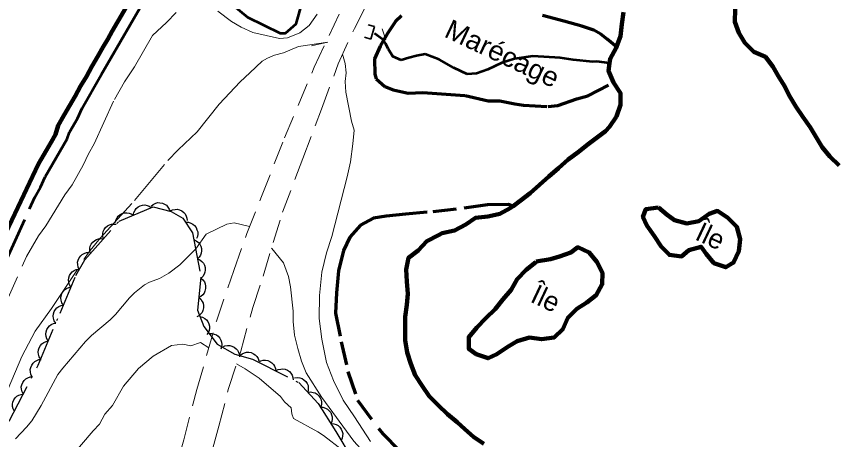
# Model space of a CAD drawing. Extents: x 355726 to 357533, y 5103782 to 5105258.
# Drawn here: x 355974.4 to 356037.4, y 5104645.3 to 5104677.9 of the extents above; entities that cross this region are included whole.
import ezdxf

# ---------------------------------------------------------------- set-up
doc = ezdxf.new("R2010")
doc.units = 0
doc.header["$LTSCALE"] = 0.6
for name, pattern in [('DASH_DOUBLE_DOT', [9.2, 5, -1.2, 0.3, -1.2, 0.3, -1.2]), ('DOT_DASHED', [7.7, 5, -1.2, 0.3, -1.2]), ('LONG_DASHED', [7.5, 6, -1.5]), ('MEDIUM_DASHED', [4.5, 3, -1.5])]:
    doc.linetypes.add(name, pattern=pattern)
for name, color, linetype, lineweight in [('1', 7, 'LONG_DASHED', 53), ('19', 7, 'Continuous', 13), ('2', 7, 'LONG_DASHED', 13), ('26', 7, 'Continuous', 35), ('4', 7, 'DASH_DOUBLE_DOT', 53), ('44', 7, 'Continuous', 25), ('7', 7, 'MEDIUM_DASHED', 70)]:
    doc.layers.add(name, color=color, linetype=linetype, lineweight=lineweight)
doc.layers.add('8', color=7, linetype='Continuous')

msp = doc.modelspace()

# ---------------------------------------------------------------- linework, layer by layer
at = {"layer": '1', "linetype": 'Continuous'}
for points in [[(355990.95, 5104678.76), (355992.11, 5104677.81), (355994.63, 5104676.58), (355995.02, 5104676.56), (355995.85, 5104677.29), (355996.33, 5104679.01)], [(355980.9, 5104673.37), (355983.85, 5104678.49)]]:
    msp.add_lwpolyline(points, dxfattribs=at)
at = {"layer": '1'}
msp.add_lwpolyline([(355973.54, 5104658.98), (355975.81, 5104663.98), (355976.24, 5104664.73), (355976.6, 5104665.53), (355978.29, 5104668.46), (355978.47, 5104668.96), (355979.08, 5104670.01), (355979.43, 5104670.81), (355980.9, 5104673.37)], dxfattribs=at)
at = {"layer": '19', "linetype": 'MEDIUM_DASHED'}
for points in [[(355997.8, 5104670.73), (355999.08, 5104674.22), (356000.32, 5104676.94), (356001.43, 5104679.09), (356002.21, 5104680.3), (356006.1, 5104687.7), (356008.11, 5104691.5), (356009.62, 5104696.76), (356011.14, 5104701.84), (356012.62, 5104707.21), (356014.22, 5104712.09), (356015.74, 5104717.23), (356017.57, 5104723.26), (356018.4, 5104728.58), (356020.43, 5104734.04), (356022.51, 5104739.47), (356025.19, 5104744.96), (356027.66, 5104749.58), (356030.65, 5104755.01), (356033.08, 5104758.13), (356035.37, 5104761.13), (356036.71, 5104764.38), (356036.94, 5104767.51)], [(355973.33, 5104607.29), (355976.87, 5104615.17), (355979.51, 5104621.42), (355981.38, 5104626.83), (355982.76, 5104630.14), (355983.73, 5104632.9), (355985.72, 5104639.37), (355987.22, 5104645.34), (355988.24, 5104649.21), (355989.73, 5104654.44), (355991.06, 5104658.34), (355992.07, 5104661.18), (355993.19, 5104664.01), (355994.95, 5104668.52), (355997.24, 5104673.96), (355999.22, 5104678.15)], [(355973.64, 5104601.69), (355975.44, 5104605.41), (355977.53, 5104610.55), (355979.26, 5104614.32), (355981.26, 5104619.25), (355981.79, 5104620.73), (355982.61, 5104622.54), (355982.76, 5104622.85), (355983.09, 5104623.55), (355984.31, 5104626.76), (355985.46, 5104630.01), (355986.84, 5104635.04), (355987.76, 5104638.42), (355988.77, 5104642.09), (355989.92, 5104646.38), (355990.66, 5104649.27), (355991.6, 5104652.15), (355992.52, 5104655.49), (355993.31, 5104657.91), (355994.8, 5104662.81), (355996.35, 5104666.94), (355997.8, 5104670.73)]]:
    msp.add_lwpolyline(points, dxfattribs=at)
at = {"layer": '2', "linetype": 'Continuous'}
for p, q in [((356002.46, 5104676.91), (356002.74, 5104676.05)), ((355988.51, 5104652.82), (355989.15, 5104652.4))]:
    msp.add_line(p, q, dxfattribs=at)
for points in [[(355982.68, 5104672.82), (355983.45, 5104673.98), (355984.83, 5104676.39), (355985.9, 5104677.38), (355986.65, 5104678.15)], [(355989.83, 5104678.25), (355990.88, 5104677.46), (355991.64, 5104677.03), (355992.52, 5104676.63), (355994.57, 5104676.17), (355995.19, 5104676.21), (355996.12, 5104676.59), (355996.85, 5104677.17), (355997.45, 5104678.03)], [(355999.41, 5104674.96), (355999.61, 5104674.25), (355999.69, 5104673.51), (355999.62, 5104672.86), (355999.66, 5104672.04), (356000.09, 5104669.82), (356000.29, 5104669.11), (356000.2, 5104668.07), (356000.02, 5104666.69), (355999.77, 5104665.54), (355998.58, 5104660.95), (355998.17, 5104659.7), (355997.83, 5104658.2), (355997.63, 5104656.43), (355997.62, 5104654.65), (355997.82, 5104653.06), (355998.19, 5104651.26), (355998.71, 5104649.88), (355999.45, 5104648.37), (356000.32, 5104647.09)], [(355988.95, 5104661.13), (355990.54, 5104661.91), (355991.09, 5104662), (355992.28, 5104661.72)], [(355993.96, 5104660.06), (355993.99, 5104660.02), (355994.87, 5104658.93), (355995.09, 5104658.36), (355995.26, 5104657.87), (355995.42, 5104657.09), (355995.62, 5104655.21), (355995.63, 5104654.43), (355995.73, 5104653.38), (355995.97, 5104652.34), (355996.25, 5104651.37), (355996.61, 5104650.49), (355997.81, 5104648.59), (356000.28, 5104645.22), (356001.82, 5104643.55), (356009.3, 5104636.37), (356010.29, 5104635.32), (356012.11, 5104634.49), (356012.47, 5104634.28)], [(355991.28, 5104651.16), (355991.93, 5104650.79), (355993.02, 5104650.08), (355994.64, 5104648.66), (355994.96, 5104648.26), (355995.47, 5104647.78), (355995.53, 5104647.34), (355995.65, 5104646.96)]]:
    msp.add_lwpolyline(points, dxfattribs=at)
at = {"layer": '2'}
for points in [[(355973.46, 5104648.59), (355974.8, 5104651.74), (355975.82, 5104653.69), (355977.07, 5104655.43), (355979.95, 5104659.75), (355980.8, 5104660.83), (355983.44, 5104663.71), (355986.01, 5104666.78), (355986.8, 5104667.61), (355988.26, 5104669), (355989.93, 5104671.12), (355991.56, 5104672.83), (355992.3, 5104673.53), (355993.25, 5104674.41), (355993.66, 5104674.66), (355994.19, 5104674.88), (355994.87, 5104675.05), (355996.02, 5104675.55), (355998.28, 5104675.89), (355997.03, 5104675.59)], [(355972.99, 5104654.58), (355975.17, 5104659.42), (355976.08, 5104661), (355976.63, 5104661.78), (355978.09, 5104664.15), (355978.65, 5104664.93), (355979.51, 5104666.44), (355979.91, 5104667.31), (355980.34, 5104668.06), (355981.9, 5104671.47), (355982.68, 5104672.82)], [(355974.32, 5104645.41), (355975.17, 5104646.3), (355975.58, 5104646.8), (355976.28, 5104647.96), (355977.57, 5104650.34), (355977.95, 5104650.84), (355979.69, 5104652.88), (355980.15, 5104653.34), (355981.58, 5104654.55), (355982, 5104654.96), (355983.07, 5104656.25), (355983.44, 5104656.63), (355984.22, 5104657.24), (355984.59, 5104657.43), (355985.36, 5104657.72), (355986.09, 5104658.13), (355986.93, 5104658.78), (355988.14, 5104660.01), (355988.95, 5104661.13)], [(355974.23, 5104637.76), (355975.58, 5104640.16), (355976.16, 5104640.83), (355976.92, 5104642.18), (355977.64, 5104642.76), (355977.98, 5104643.36), (355980.27, 5104646.03), (355980.76, 5104646.54), (355981.18, 5104647.3), (355981.76, 5104647.96), (355982.6, 5104649.46), (355983.75, 5104650.8), (355984.88, 5104651.75), (355986.29, 5104652.58), (355987.15, 5104652.69), (355987.76, 5104652.55), (355988.51, 5104652.82)], [(355995.65, 5104646.96), (355997.52, 5104645.95), (355997.96, 5104645.66), (355999.4, 5104644.55), (356001.08, 5104643.13), (356002.23, 5104642.08), (356003.88, 5104640.45), (356004.4, 5104639.86), (356006.29, 5104637.4), (356007.38, 5104636.23), (356009.78, 5104634.03), (356012.16, 5104631.97), (356014.23, 5104630.34), (356016.56, 5104628.61), (356019.19, 5104626.54), (356022.06, 5104624.42), (356024.85, 5104622.25), (356029.21, 5104619.18), (356030.91, 5104617.84), (356033.3, 5104615.73), (356036.1, 5104613.93)], [(356000.32, 5104647.09), (356001.55, 5104645.21)]]:
    msp.add_lwpolyline(points, dxfattribs=at)
at = {"layer": '26'}
for p, q in [((356001.86, 5104677.09), (356001.38, 5104677.22)), ((356001.86, 5104677.09), (356001.57, 5104676.12)), ((356001.57, 5104676.12), (356001.1, 5104676.27))]:
    msp.add_line(p, q, dxfattribs=at)
at = {"layer": '4', "linetype": 'Continuous', "lineweight": 90}
for points in [[(355985.09, 5104681.09), (355983.94, 5104680.54), (355982.61, 5104678.22), (355982.17, 5104677.46), (355981.74, 5104676.71), (355981.39, 5104676.11), (355981.05, 5104675.51), (355980.61, 5104674.75), (355980.18, 5104674), (355979.75, 5104673.25), (355979.31, 5104672.49), (355978.88, 5104671.74), (355978.45, 5104670.99), (355978.02, 5104670.24), (355977.58, 5104669.48), (355977.39, 5104668.79), (355977.04, 5104668.19), (355976.7, 5104667.59), (355976.26, 5104666.84), (355976.09, 5104666.54), (355972.2, 5104658.36)], [(356037.51, 5104666.4), (356036.8, 5104667.09), (356036.22, 5104667.82), (356035.75, 5104668.58), (356035.28, 5104669.34), (356034.74, 5104670.14), (356034.19, 5104670.94), (356033.73, 5104671.7), (356033.3, 5104672.54), (356032.83, 5104673.3), (356032.44, 5104674.01), (356031.86, 5104674.74), (356030.98, 5104675.13), (356030.28, 5104675.83), (356029.81, 5104676.59), (356029.51, 5104677.45), (356029.55, 5104678.42)], [(356020.97, 5104678.19), (356020.85, 5104677.27), (356020.73, 5104676.34), (356020.44, 5104675.52), (356020.41, 5104675.43), (356019.94, 5104674.6), (356019.9, 5104674.27), (356019.82, 5104673.68), (356020.2, 5104672.77), (356020.75, 5104671.96), (356020.74, 5104671.07), (356020.43, 5104670.16)], [(356020.43, 5104670.16), (356019.89, 5104669.37), (356019.6, 5104669.04), (356018.26, 5104668.03)], [(356018.26, 5104668.03), (356017.48, 5104667.43), (356016.71, 5104666.87), (356015.98, 5104666.19), (356015.23, 5104665.57), (356014.52, 5104664.93), (356013.81, 5104664.28), (356013.03, 5104663.68), (356012.49, 5104663.29), (356012.27, 5104663.12), (356011.47, 5104662.68), (356011.37, 5104662.66), (356010.57, 5104662.49), (356009.61, 5104662.38), (356008.87, 5104661.86), (356008.01, 5104661.4), (356007.06, 5104661.2), (356006.78, 5104661.05), (356005.89, 5104660.59), (356005.2, 5104659.88), (356004.47, 5104659.3), (356004.28, 5104658.42), (356004.35, 5104657.49), (356004.42, 5104656.55), (356004.34, 5104655.71), (356004.22, 5104654.78), (356004.21, 5104653.89), (356004.21, 5104653), (356004.36, 5104652.03), (356004.66, 5104651.16), (356004.97, 5104650.29), (356005.51, 5104649.49), (356006.06, 5104648.69), (356006.76, 5104648), (356007.46, 5104647.3), (356008.21, 5104646.68), (356008.8, 5104646.15), (356009.47, 5104645.57), (356010.26, 5104645.03)]]:
    msp.add_lwpolyline(points, dxfattribs=at)
at = {"layer": '4'}
msp.add_lwpolyline([(356019.9, 5104674.27), (356018.93, 5104674.38), (356018.61, 5104674.36), (356017.11, 5104674.51), (356016.11, 5104674.68), (356014.01, 5104674.81), (356012.61, 5104674.61), (356011.62, 5104674.28), (356010.55, 5104673.79), (356009.68, 5104673.48), (356008.98, 5104673.43), (356007.95, 5104673.91), (356006.82, 5104674.55), (356005.75, 5104674.95), (356005.09, 5104674.83), (356004.5, 5104674.67), (356003.91, 5104674.5), (356003.26, 5104674.77), (356002.9, 5104675.37), (356002.73, 5104675.76), (356002.51, 5104676.08), (356001.87, 5104676.54)], dxfattribs=at)
at = {"layer": '4', "linetype": 'Continuous', "lineweight": 90}
for points in [[(356023.65, 5104663.19), (356022.68, 5104663.04), (356022.46, 5104662.47), (356022.77, 5104661.8), (356023.31, 5104661), (356023.86, 5104660.19), (356024.49, 5104659.54), (356025.41, 5104659.42), (356025.98, 5104659.89), (356026.92, 5104660.16), (356027.32, 5104659.63), (356027.91, 5104658.91), (356028.82, 5104658.59), (356029.42, 5104658.95), (356029.81, 5104659.82), (356029.93, 5104660.74), (356029.67, 5104661.68), (356028.97, 5104662.38), (356028.18, 5104662.92), (356027.55, 5104662.68), (356026.74, 5104662.14), (356025.84, 5104661.95), (356024.89, 5104662.2), (356024.32, 5104662.61)], [(356014.27, 5104659.04), (356014.23, 5104658.97), (356013.5, 5104658.38), (356012.81, 5104657.68), (356012.34, 5104656.85), (356011.72, 5104656.11), (356011.11, 5104655.37), (356010.41, 5104654.67), (356009.72, 5104653.97), (356009.1, 5104653.22), (356009.1, 5104652.33), (356009.66, 5104651.92), (356010.58, 5104651.6), (356011.25, 5104651.91), (356012.05, 5104652.45), (356012.81, 5104652.92), (356013.76, 5104653.18), (356014.68, 5104653.06), (356015.66, 5104653.2), (356016.31, 5104653.83), (356016.7, 5104654.7), (356017.39, 5104655.4), (356018.15, 5104655.87), (356018.88, 5104656.45), (356019.34, 5104657.28), (356019.35, 5104658.17), (356018.92, 5104659), (356018.34, 5104659.73), (356017.46, 5104660.12), (356016.94, 5104659.72), (356016.07, 5104659.42), (356015.36, 5104659.22)]]:
    msp.add_lwpolyline(points, close=True, dxfattribs=at)
at = {"layer": '44'}
for points in [[(355983.35, 5104662.59), (355983.39, 5104662.79), (355983.49, 5104662.97), (355983.58, 5104663.11), (355983.72, 5104663.22), (355983.88, 5104663.3), (355984.07, 5104663.35), (355984.23, 5104663.37), (355984.41, 5104663.34), (355984.58, 5104663.27), (355984.73, 5104663.18)], [(355984.72, 5104663.28), (355984.88, 5104663.42), (355985.07, 5104663.5), (355985.23, 5104663.55), (355985.4, 5104663.54), (355985.59, 5104663.51), (355985.76, 5104663.43), (355985.9, 5104663.35), (355986.01, 5104663.21), (355986.11, 5104663.06), (355986.17, 5104662.88)], [(355981.97, 5104662), (355982.01, 5104662.21), (355982.11, 5104662.39), (355982.2, 5104662.52), (355982.34, 5104662.63), (355982.5, 5104662.72), (355982.69, 5104662.76), (355982.85, 5104662.78), (355983.03, 5104662.75), (355983.2, 5104662.69), (355983.35, 5104662.59)], [(355986.18, 5104662.91), (355986.37, 5104663), (355986.57, 5104663.03), (355986.73, 5104663.04), (355986.9, 5104662.99), (355987.07, 5104662.92), (355987.22, 5104662.79), (355987.33, 5104662.68), (355987.41, 5104662.52), (355987.47, 5104662.35), (355987.48, 5104662.17)], [(355987.37, 5104662.04), (355987.58, 5104662.04), (355987.77, 5104661.98), (355987.92, 5104661.91), (355988.05, 5104661.79), (355988.17, 5104661.65), (355988.24, 5104661.47), (355988.3, 5104661.32), (355988.3, 5104661.14), (355988.27, 5104660.96), (355988.2, 5104660.79)], [(355981.06, 5104660.77), (355981.01, 5104660.97), (355981.02, 5104661.17), (355981.04, 5104661.33), (355981.12, 5104661.49), (355981.23, 5104661.64), (355981.38, 5104661.76), (355981.52, 5104661.85), (355981.69, 5104661.89), (355981.88, 5104661.91), (355982.05, 5104661.89)], [(355980.06, 5104659.64), (355980.01, 5104659.85), (355980.02, 5104660.05), (355980.05, 5104660.21), (355980.13, 5104660.37), (355980.24, 5104660.52), (355980.39, 5104660.64), (355980.52, 5104660.73), (355980.69, 5104660.77), (355980.88, 5104660.79), (355981.06, 5104660.77)], [(355988, 5104660.71), (355988.19, 5104660.63), (355988.35, 5104660.5), (355988.46, 5104660.37), (355988.53, 5104660.21), (355988.58, 5104660.04), (355988.58, 5104659.84), (355988.57, 5104659.68), (355988.5, 5104659.52), (355988.4, 5104659.36), (355988.27, 5104659.24)], [(355979.21, 5104658.42), (355979.12, 5104658.6), (355979.09, 5104658.8), (355979.08, 5104658.97), (355979.12, 5104659.14), (355979.2, 5104659.31), (355979.32, 5104659.46), (355979.44, 5104659.57), (355979.59, 5104659.65), (355979.77, 5104659.71), (355979.95, 5104659.73)], [(355988.27, 5104659.24), (355988.47, 5104659.15), (355988.62, 5104659.02), (355988.73, 5104658.9), (355988.81, 5104658.74), (355988.86, 5104658.56), (355988.86, 5104658.37), (355988.85, 5104658.21), (355988.78, 5104658.05), (355988.68, 5104657.89), (355988.55, 5104657.76)], [(355978.57, 5104657.06), (355978.46, 5104657.24), (355978.4, 5104657.43), (355978.38, 5104657.6), (355978.4, 5104657.77), (355978.46, 5104657.95), (355978.57, 5104658.11), (355978.67, 5104658.24), (355978.81, 5104658.33), (355978.98, 5104658.41), (355979.16, 5104658.44)], [(355988.53, 5104657.76), (355988.69, 5104657.63), (355988.81, 5104657.46), (355988.88, 5104657.31), (355988.9, 5104657.13), (355988.9, 5104656.95), (355988.85, 5104656.76), (355988.79, 5104656.61), (355988.68, 5104656.48), (355988.54, 5104656.35), (355988.38, 5104656.27)], [(355977.99, 5104655.68), (355977.88, 5104655.86), (355977.82, 5104656.05), (355977.79, 5104656.22), (355977.82, 5104656.39), (355977.88, 5104656.57), (355977.98, 5104656.73), (355978.08, 5104656.85), (355978.23, 5104656.95), (355978.4, 5104657.03), (355978.57, 5104657.06)], [(355988.38, 5104656.27), (355988.54, 5104656.13), (355988.65, 5104655.96), (355988.72, 5104655.82), (355988.75, 5104655.64), (355988.75, 5104655.46), (355988.7, 5104655.27), (355988.64, 5104655.12), (355988.52, 5104654.98), (355988.38, 5104654.86), (355988.23, 5104654.78)], [(355977.41, 5104654.3), (355977.29, 5104654.47), (355977.24, 5104654.67), (355977.21, 5104654.83), (355977.24, 5104655.01), (355977.29, 5104655.18), (355977.39, 5104655.34), (355977.49, 5104655.47), (355977.64, 5104655.57), (355977.81, 5104655.65), (355977.99, 5104655.68)], [(355988.47, 5104654.81), (355988.67, 5104654.76), (355988.85, 5104654.66), (355988.98, 5104654.56), (355989.08, 5104654.41), (355989.16, 5104654.25), (355989.2, 5104654.06), (355989.21, 5104653.9), (355989.17, 5104653.73), (355989.1, 5104653.55), (355989, 5104653.41)], [(355976.83, 5104652.91), (355976.72, 5104653.09), (355976.66, 5104653.28), (355976.63, 5104653.45), (355976.66, 5104653.62), (355976.71, 5104653.8), (355976.82, 5104653.96), (355976.92, 5104654.09), (355977.06, 5104654.19), (355977.23, 5104654.26), (355977.41, 5104654.3)], [(355989.17, 5104653.5), (355989.38, 5104653.51), (355989.57, 5104653.46), (355989.73, 5104653.4), (355989.86, 5104653.29), (355989.99, 5104653.15), (355990.07, 5104652.98), (355990.13, 5104652.83), (355990.14, 5104652.65), (355990.13, 5104652.47), (355990.07, 5104652.3)], [(355976.26, 5104651.53), (355976.14, 5104651.7), (355976.08, 5104651.9), (355976.06, 5104652.06), (355976.08, 5104652.24), (355976.14, 5104652.41), (355976.24, 5104652.57), (355976.34, 5104652.7), (355976.49, 5104652.8), (355976.66, 5104652.88), (355976.83, 5104652.91)], [(355990.2, 5104652.44), (355990.38, 5104652.54), (355990.58, 5104652.57), (355990.75, 5104652.58), (355990.92, 5104652.53), (355991.09, 5104652.46), (355991.24, 5104652.33), (355991.35, 5104652.22), (355991.43, 5104652.06), (355991.49, 5104651.89), (355991.5, 5104651.71)], [(355991.54, 5104651.8), (355991.7, 5104651.93), (355991.89, 5104652.02), (355992.04, 5104652.06), (355992.22, 5104652.06), (355992.4, 5104652.03), (355992.57, 5104651.94), (355992.71, 5104651.86), (355992.83, 5104651.73), (355992.93, 5104651.57), (355992.99, 5104651.4)], [(355975.6, 5104650.18), (355975.5, 5104650.36), (355975.46, 5104650.56), (355975.45, 5104650.73), (355975.49, 5104650.9), (355975.56, 5104651.07), (355975.68, 5104651.22), (355975.79, 5104651.34), (355975.94, 5104651.43), (355976.11, 5104651.49), (355976.29, 5104651.51)], [(355992.95, 5104651.31), (355993.13, 5104651.41), (355993.33, 5104651.45), (355993.5, 5104651.46), (355993.67, 5104651.43), (355993.84, 5104651.36), (355993.99, 5104651.24), (355994.11, 5104651.13), (355994.2, 5104650.98), (355994.26, 5104650.81), (355994.29, 5104650.63)], [(355994.29, 5104650.63), (355994.47, 5104650.73), (355994.67, 5104650.77), (355994.83, 5104650.79), (355995.01, 5104650.75), (355995.18, 5104650.68), (355995.33, 5104650.57), (355995.45, 5104650.46), (355995.54, 5104650.3), (355995.6, 5104650.13), (355995.63, 5104649.95)], [(355974.92, 5104648.85), (355974.82, 5104649.03), (355974.78, 5104649.23), (355974.76, 5104649.39), (355974.8, 5104649.56), (355974.87, 5104649.74), (355974.99, 5104649.89), (355975.1, 5104650.01), (355975.25, 5104650.09), (355975.43, 5104650.16), (355975.6, 5104650.18)], [(355995.73, 5104650.09), (355995.94, 5104650.12), (355996.14, 5104650.09), (355996.3, 5104650.04), (355996.45, 5104649.95), (355996.58, 5104649.82), (355996.69, 5104649.66), (355996.76, 5104649.51), (355996.78, 5104649.34), (355996.78, 5104649.15), (355996.74, 5104648.98)], [(355974.23, 5104647.51), (355974.13, 5104647.7), (355974.09, 5104647.9), (355974.08, 5104648.06), (355974.11, 5104648.23), (355974.18, 5104648.4), (355974.3, 5104648.56), (355974.41, 5104648.68), (355974.56, 5104648.76), (355974.74, 5104648.82), (355974.92, 5104648.85)], [(355996.74, 5104648.98), (355996.95, 5104649.01), (355997.15, 5104648.98), (355997.31, 5104648.93), (355997.45, 5104648.84), (355997.59, 5104648.71), (355997.69, 5104648.55), (355997.77, 5104648.4), (355997.79, 5104648.23), (355997.79, 5104648.04), (355997.75, 5104647.87)], [(355997.7, 5104647.84), (355997.91, 5104647.83), (355998.11, 5104647.77), (355998.25, 5104647.69), (355998.38, 5104647.57), (355998.5, 5104647.43), (355998.57, 5104647.25), (355998.62, 5104647.09), (355998.62, 5104646.92), (355998.58, 5104646.74), (355998.51, 5104646.57)], [(355998.53, 5104646.58), (355998.74, 5104646.57), (355998.93, 5104646.5), (355999.07, 5104646.42), (355999.2, 5104646.3), (355999.31, 5104646.15), (355999.38, 5104645.97), (355999.42, 5104645.81), (355999.41, 5104645.64), (355999.37, 5104645.46), (355999.3, 5104645.29)]]:
    msp.add_lwpolyline(points, dxfattribs=at)
at = {"layer": '44', "linetype": 'DOT_DASHED'}
msp.add_lwpolyline([(355973.84, 5104646.76), (355976.06, 5104651.06), (355977.73, 5104655.07), (355978.95, 5104657.95), (355979.63, 5104659.16), (355982.27, 5104662.13), (355984.88, 5104663.24), (355986.26, 5104662.86), (355987.16, 5104662.35), (355987.9, 5104661.24), (355988.54, 5104657.82), (355988.28, 5104655.3), (355988.76, 5104654.04), (355989.78, 5104652.68), (355991.14, 5104651.91), (355992.51, 5104651.53), (355996.06, 5104649.73), (355997.53, 5104648.11), (355998.9, 5104645.96), (356000.33, 5104643.57)], dxfattribs=at)
at = {"layer": '7'}
for points in [[(356003.93, 5104677.91), (356003.48, 5104677.47), (356002.85, 5104676.54), (356002.3, 5104675.56), (356001.87, 5104674.61), (356001.89, 5104673.41), (356001.99, 5104673.05), (356002.66, 5104672.48), (356003.3, 5104672.21), (356004.45, 5104671.96), (356005.58, 5104672.02), (356007.01, 5104671.91), (356008.83, 5104671.78), (356010.59, 5104671.38), (356011.48, 5104671.38), (356012.63, 5104671.13), (356013.29, 5104671.05), (356015.19, 5104670.93), (356015.93, 5104671), (356017.4, 5104671.52), (356018.22, 5104671.75), (356020.2, 5104672.77)], [(356020.44, 5104675.52), (356019.71, 5104676.12), (356019.22, 5104676.5), (356018.69, 5104676.79), (356017.78, 5104677.11), (356016.4, 5104677.49), (356014.75, 5104677.92)], [(356012.49, 5104663.29), (356012.15, 5104663.41), (356010.53, 5104663.38), (356008.13, 5104663.05), (356005.91, 5104662.81), (356004.23, 5104662.66), (356002.75, 5104662.51), (356001.78, 5104662.36), (356000.78, 5104661.83), (355999.96, 5104660.9), (355999.49, 5104659.88), (355999.1, 5104658.31), (355998.94, 5104656.62), (355998.87, 5104655.07), (355999.31, 5104652.85), (355999.82, 5104650.58), (356000.56, 5104648.37), (356002.49, 5104645.8), (356004.89, 5104643.36)]]:
    msp.add_lwpolyline(points, dxfattribs=at)

# ---------------------------------------------------------------- texts
at = {"layer": '7', "width": 1.05}
msp.add_text('Marécage', height=1.5, rotation=334.72, dxfattribs=at).set_placement((356007.12, 5104676.33))
at = {"layer": '8'}
for p in [(356026.37, 5104660.76), (356013.73, 5104655.97)]:
    msp.add_text('Île', height=1.5, rotation=334.72, dxfattribs=at).set_placement(p)

doc.saveas('drawing.dxf')
